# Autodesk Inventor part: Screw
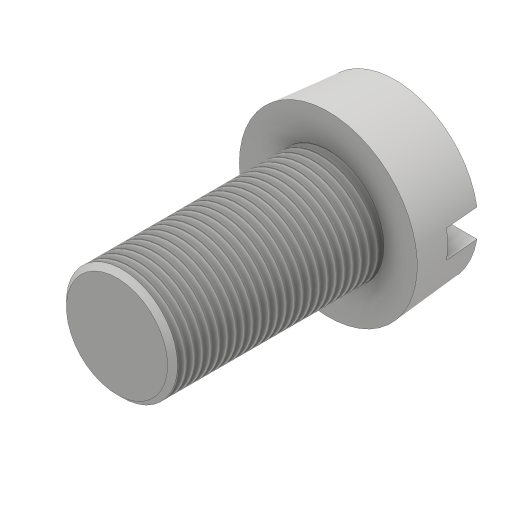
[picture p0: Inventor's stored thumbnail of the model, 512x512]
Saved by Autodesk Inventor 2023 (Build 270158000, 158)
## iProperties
Created: 2016-05
Part Number: Screw
Material: Generic
Document SubType Name: Modeling
Designer: CADCIM
Density: 1 g/cm^3
Appearance: Default
Author: CADCIM
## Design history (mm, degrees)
sketch "Sketch1"
  geometry: C1 r 16 at (0, 0); 1 further point
  constraints: 1 centre point, 1 coincident
  dimensions: "d0" = 32 diameter of C1
extrude "Extrusion1" new body sketch "Sketch1" distance "d1" = 12; taper "d2" = -5 deg
sketch "Sketch2"
  geometry: C1 r 10 at (0, 0); 1 further point
  constraints: 1 centre point, 1 coincident
  dimensions: "d4" = 20 diameter of C1
extrude "Extrusion2" join sketch "Sketch2" distance "d5" = 38; taper "d6" = 0 deg
workplane "Work Plane1"
thread "Thread1" dims "d10" = 10, "d11" = 0
chamfer "Chamfer1" distance "d12" = 0.9; stored, may be unused: second distance "d13" = 2, angle "d14" = 45 deg
sketch "Sketch4"
  geometry: L1 (-19.014, -2.5)-(20.179, -2.5); L2 (20.179, -2.5)-(20.179, 2.5); L3 (20.179, 2.5)-(-19.014, 2.5); L4 (-19.014, 2.5)-(-19.014, -2.5); L5 (0, 0)-(-19.039, 0)
  constraints: 10 end point, 2 horizontal, 2 parallel, 1 perpendicular, 1 other
  dimensions: "d15" = 5 distance of L3.end L1.start
extrude "Extrusion4" cut sketch "Sketch4" distance "d16" = 6; taper "d17" = 0 deg
body "Solid1"
